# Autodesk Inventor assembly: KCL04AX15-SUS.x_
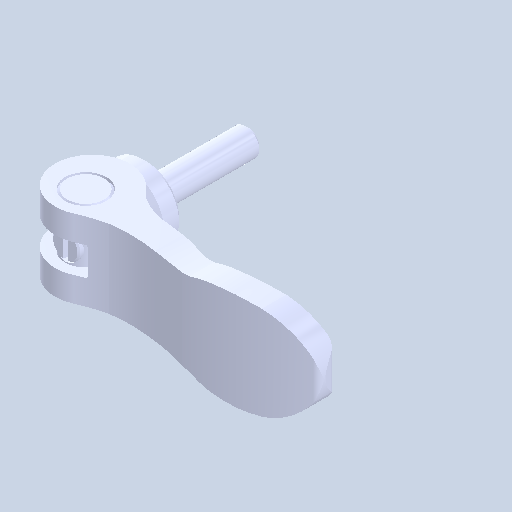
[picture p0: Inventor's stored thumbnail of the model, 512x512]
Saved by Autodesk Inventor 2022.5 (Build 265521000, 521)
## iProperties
Created: 2024-08
Part Number: KCL04AX15-SUS.x_
Document SubType Name: Assembly
Designer: ImaoCorp
Author: ImaoCorp
Sending System: SOLIDWORKS 2022-2022290
MC: AMD64
MC_MODEL: Intel64 Family 6 Model 60 Stepping 3, GenuineIntel
OS: Windows_NT
FRU: Parasolid Version 33.1, build 260,  4-25-2022
FORMAT: text
GUISE: transmit
KEY: FILEKCL04AX15-SUS.x_t
DATE: Thu Aug 29 10:47:32 2024
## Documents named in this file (5)
- Y:\5.更新分\2024年対応\1001_KCL\データ\kcl04ax15-sus\KCL04AX15-SUS.x_.iam
- Y:\5.更新分\2024年対応\1001_KCL\データ\kcl04ax15-sus\KCL04AX15-SUS_01.ipt
- Y:\5.更新分\2024年対応\1001_KCL\データ\kcl04ax15-sus\KCL04AX15-SUS_02.ipt
- Y:\5.更新分\2024年対応\1001_KCL\データ\kcl04ax15-sus\KCL04AX15-SUS_03.ipt
- Y:\5.更新分\2024年対応\1001_KCL\データ\kcl04ax15-sus\KCL04AX15-SUS_04.ipt
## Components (4 placed, 4 different names)
1. KCL04AX15-SUS_01
2. KCL04AX15-SUS_02
3. KCL04AX15-SUS_03
4. KCL04AX15-SUS_04
